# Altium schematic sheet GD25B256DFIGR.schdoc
size 127 x 101 mm
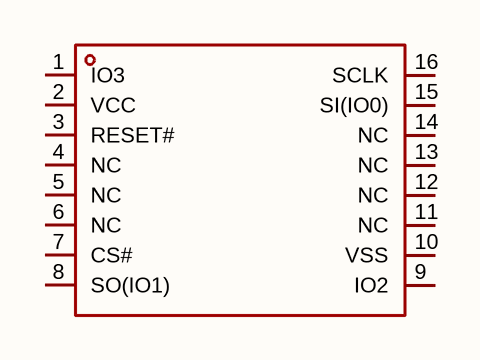
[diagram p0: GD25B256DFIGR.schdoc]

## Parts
U?  gd25b256dfigr  [SOP-16_L10.3-W7.5-P1.27-LS10.3-BL]  (value not drawn)

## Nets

Not connected (* = marked no-connect by the designer): U? 1(IO3) 2(VCC) 3(RESET#) 4(NC) 5(NC) 6(NC) 7(CS#) 8(SO(IO1)) 9(IO2) 10(VSS) 11(NC) 12(NC) 13(NC) 14(NC) 15(SI(IO0)) 16(SCLK)

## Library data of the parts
U? = gd25b256dfigr: 接口类型:SPI;存储容量:256Mbit;时钟频率(fc):104MHz;; Manufacturer: GigaDevice(兆易创新); AddInBom: yes; ModelId: 89cbb1eeec7e4dc89e56d8a524192cc7; ModelTransform: 405.511,405.511,0,0,0,0,0,0,0; Interface: SPI; Clock Frequency: 104MHz; Voltage - Supply: 2.7V~3.6V; Standby Supply Current: 12uA; Program / Erase Cycles: 100000次; Page Programming Time (Tpp): 400us; Block Erase Time(tBE): 160ms@(32KB); Data Retention - TDR (Year): 20年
